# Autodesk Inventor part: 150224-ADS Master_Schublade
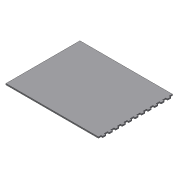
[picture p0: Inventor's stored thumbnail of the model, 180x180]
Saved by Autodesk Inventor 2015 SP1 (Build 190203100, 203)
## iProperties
Created: 2015-02
Part Number: 150224-ADS Master_Schublade
Material: Generic
Document SubType Name: Modeling
Designer: SATurn
Density: 1 g/cm^3
Appearance: Default
Description: 150224-ADS Master_Schublade
ILogicFactory: False
Author: SATurn
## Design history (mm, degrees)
sketch "Master_Schublade"
  geometry: L1 (242, 290)-(-242, 290); L2 (-242, 290)-(-242, -290); L3 (-242, -290)-(242, -290); L4 (242, -290)-(242, 290); L5 (242, 290)-(-242, -290); L6 (-242, 290)-(242, -290); 1 further point
  constraints: 12 end point, 2 midpoint, 2 parallel, 1 horizontal, 1 perpendicular
  dimensions: "d0" = 484 distance of L3.end L2.end (= L); "d1" = 580 distance of L2.end L1.end (= B)
extrude "Extrusion1" new body sketch "Master_Schublade" stored distance "d4" = 8 (= H_Boden); taper "d5" = 0 deg
sketch "Sketch3"
  geometry: L1 (-242, 290)-(-242, -290) reference; L2 (242, 290)-(-242, 290) reference; L3 (242, -290)-(242, 290) reference; L4 (-242, -290)-(242, -290) reference; L5 (-242, 290)-(-222, 290); L6 (-222, 290)-(-222, 280); L7 (-222, 280)-(-242, 280); L8 (-242, 280)-(-242, 290); L9 (-242, 260)-(-232, 260); L10 (-232, 260)-(-232, 240); L11 (-232, 240)-(-242, 240); L12 (-242, 240)-(-242, 260); L13 (0, 290)-(0, -290); 1 further point
  constraints: 18 end point, 4 parallel, 2 horizontal, 2 midpoint, 2 perpendicular, 1 collinear
  dimensions: "d8" = 580 distance of L3.start L2.start (derived); "d9" = 484 distance of L2.start L1.start (derived); "d11" = 10 distance of L5.end L6.end (= T_Zinken); "d12" = 20 distance of L1.start L5.end (= B_Zinken); "d13" = 20 distance of L11.end L9.start (= B_Zinken); "d14" = 10 distance of L10.end L11.end (= T_Zinken); "d15" = 20 distance between parallel lines of L9 L7 (= B_Zinken)
extrude "Extrusion2" cut sketch "Sketch3" stored distance "d21" = 0; taper "d22" = 0 deg
extrude_surface "ExtrusionSrf1" dims "d16" = 10, "d17" = 0
pattern_linear "Rectangular Pattern1" dims "d20" = 40 (= 2 x B_Zinken)
sketch "Sketch6"
  geometry: L1 (-4, -290)-(-4, -282); L2 (-4, -282)-(576, -282); L3 (576, -282)-(576, -290); L4 (576, -290)-(-4, -290); 1 further point
  constraints: 8 end point, 2 parallel, 1 perpendicular, 1 vertical
  dimensions: "d23" = 8 distance of L1.start L1.end (= H_Boden); "d24" = 290 distance from line of point (0, 0) L4 (= 0.5 x B); "d25" = 4 distance from line of point (0, 0) L1 (= 0.5 x H_Boden); "d26" = 580 distance of L3.end L1.start (= B)
extrude "Extrusion3" new body sketch "Sketch6" stored distance "d27" = 484 (= L); taper "d28" = 0 deg
sketch "Sketch5"
  geometry: L1 (580, -2)-(560, -2) reference; L2 (560, -2)-(560, 8) reference; L3 (560, 8)-(580, 8) reference; L4 (580, 8)-(580, -2) reference; L5 (540, -2)-(520, -2) reference; L6 (520, -2)-(520, 8) reference; L7 (520, 8)-(540, 8) reference; L8 (540, 8)-(540, -2) reference; L9 (500, -2)-(480, -2) reference; L10 (480, -2)-(480, 8) reference; L11 (480, 8)-(500, 8) reference; L12 (500, 8)-(500, -2) reference; L13 (460, -2)-(440, -2) reference; L14 (440, -2)-(440, 8) reference; L15 (440, 8)-(460, 8) reference; L16 (460, 8)-(460, -2) reference; L17 (420, -2)-(400, -2) reference; L18 (400, -2)-(400, 8) reference; L19 (400, 8)-(420, 8) reference; L20 (420, 8)-(420, -2) reference; L21 (380, -2)-(360, -2) reference; L22 (360, -2)-(360, 8) reference; L23 (360, 8)-(380, 8) reference; L24 (380, 8)-(380, -2) reference; L25 (340, -2)-(320, -2) reference; L26 (320, -2)-(320, 8) reference; L27 (320, 8)-(340, 8) reference; L28 (340, 8)-(340, -2) reference; L29 (300, -2)-(280, -2) reference; L30 (280, -2)-(280, 8) reference; L31 (280, 8)-(300, 8) reference; L32 (300, 8)-(300, -2) reference; L33 (260, -2)-(240, -2) reference; L34 (240, -2)-(240, 8) reference; L35 (240, 8)-(260, 8) reference; L36 (260, 8)-(260, -2) reference; L37 (220, -2)-(200, -2) reference; L38 (200, -2)-(200, 8) reference; L39 (200, 8)-(220, 8) reference; L40 (220, 8)-(220, -2) reference; L41 (180, -2)-(160, -2) reference; L42 (160, -2)-(160, 8) reference; L43 (160, 8)-(180, 8) reference; L44 (180, 8)-(180, -2) reference; L45 (140, -2)-(120, -2) reference; L46 (120, -2)-(120, 8) reference; L47 (120, 8)-(140, 8) reference; L48 (140, 8)-(140, -2) reference; L49 (100, -2)-(80, -2) reference; L50 (80, -2)-(80, 8) reference; L51 (80, 8)-(100, 8) reference; L52 (100, 8)-(100, -2) reference; L53 (60, -2)-(40, -2) reference; L54 (40, -2)-(40, 8) reference; L55 (40, 8)-(60, 8) reference; L56 (60, 8)-(60, -2) reference; L57 (20, -2)-(0, -2) reference; L58 (0, -2)-(0, 8) reference; L59 (0, 8)-(20, 8) reference; L60 (20, 8)-(20, -2) reference; 1 further point
  node "Project Cut Edges3"
body "Solid1"
body "Srf1"
body "Solid2"
other parameters: "B" = 580 [user parameter; used in 3 equation terms], "L" = 484 [user parameter; used in 3 equation terms], "B_Zinken" = 20 [user parameter; used in 5 equation terms], "H_Boden" = 8 [user parameter; used in 3 equation terms], "T_Zinken" = 10 [user parameter; used in 2 equation terms], "Edge_Dist" = 1 [user parameter]
